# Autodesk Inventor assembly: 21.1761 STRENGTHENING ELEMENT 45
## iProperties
Created: 2007-04
Part Number: 21.1761 STRENGTHENING ELEMENT 45
Document SubType Name: Assembly
Designer: Andy Moles
Mass: 732.101 g
Surface Area: 1670.92 cm^2
Volume: 259.295 cm^3
Density: 2.82343 g/cm^3
Author: Andy Moles
